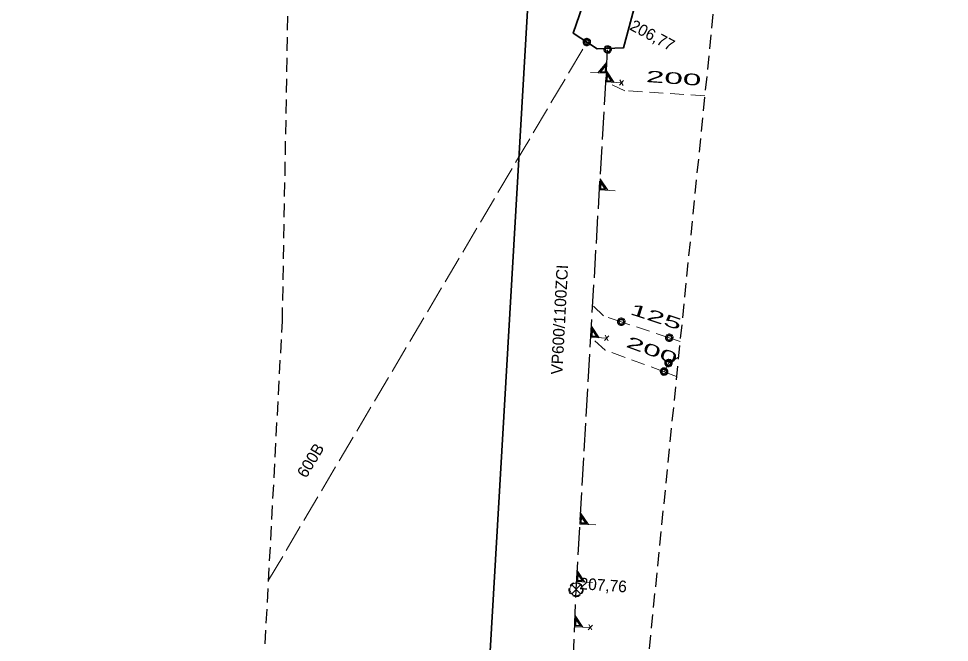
# Model space of a CAD drawing. Extents: x -744446 to -743929, y -1041261 to -1040599.
# Drawn here: x -744445.1 to -744380.7, y -1040960.6 to -1040917.5 of the extents above; entities that cross this region are included whole.
import ezdxf

# ---------------------------------------------------------------- set-up
doc = ezdxf.new("R2010")
doc.units = 0
doc.header["$LTSCALE"] = 0.32
doc.linetypes.add('LONG_DASHED', pattern=[7.5, 6, -1.5])
doc.linetypes.add('MEDIUM_DASHED', pattern=[4.5, 3, -1.5])
for name, color, linetype, lineweight in [('1', 7, 'MEDIUM_DASHED', 25), ('18', 7, 'Continuous', 13), ('20', 7, 'LONG_DASHED', 13), ('49', 7, 'MEDIUM_DASHED', 13)]:
    doc.layers.add(name, color=color, linetype=linetype, lineweight=lineweight)

msp = doc.modelspace()

# ---------------------------------------------------------------- linework, layer by layer
at = {"layer": '1'}
msp.add_lwpolyline([(-744438.077, -1041259.731), (-744438.679, -1041250.888), (-744445.125, -1041198.426), (-744434.434, -1041080.103), (-744426.87, -1040938.41), (-744425.446, -1040859.072), (-744414.192, -1040822.094), (-744390.076, -1040771.45), (-744357.118, -1040726.434), (-744307.278, -1040693.475), (-744241.36, -1040670.967), (-743937.498, -1040598.618), (-743928.655, -1040619.519), (-744129.684, -1040665.585), (-744218.109, -1040687.29), (-744311.358, -1040718.641), (-744361.198, -1040777.323), (-744391.745, -1040864.141), (-744411.355, -1041059.185), (-744416.379, -1041145.154), (-744432.569, -1041193.163), (-744432.047, -1041202.053), (-744422.803, -1041230.992), (-744424.813, -1041260.936)], close=True, dxfattribs=at)
at = {"layer": '18'}
for p, q in [((-744403.26, -1040921.749), (-744403.549, -1040922.068)), ((-744403.292, -1040922.086), (-744403.514, -1040921.701)), ((-744404.29, -1040939.429), (-744404.579, -1040939.748)), ((-744404.322, -1040939.766), (-744404.544, -1040939.381)), ((-744406.231, -1040957.285), (-744406.849, -1040956.667)), ((-744406.849, -1040957.285), (-744406.232, -1040956.668)), ((-744405.42, -1040959.451), (-744405.703, -1040959.774)), ((-744405.446, -1040959.788), (-744405.674, -1040959.407))]:
    msp.add_line(p, q, dxfattribs=at)
at = {"layer": '18', "lineweight": 35}
msp.add_lwpolyline([(-744405.436, -1040914.627), (-744403.633, -1040914.677), (-744402.237, -1040915.595), (-744403.265, -1040919.486), (-744405.096, -1040919.552), (-744406.737, -1040918.467)], close=True, dxfattribs=at)
at = {"layer": '18'}
for points in [[(-744405.537, -1040919.073), (-744405.543, -1040919.017), (-744405.559, -1040918.964), (-744405.588, -1040918.915), (-744405.627, -1040918.874), (-744405.673, -1040918.842), (-744405.725, -1040918.82), (-744405.78, -1040918.809), (-744405.836, -1040918.811), (-744405.891, -1040918.824), (-744405.941, -1040918.849), (-744405.986, -1040918.884), (-744406.022, -1040918.927), (-744406.047, -1040918.977), (-744406.062, -1040919.032), (-744406.065, -1040919.088), (-744406.056, -1040919.143), (-744406.035, -1040919.196), (-744406.004, -1040919.242), (-744405.963, -1040919.281), (-744405.916, -1040919.311), (-744405.863, -1040919.33), (-744405.807, -1040919.337), (-744405.75, -1040919.333), (-744405.696, -1040919.316), (-744405.647, -1040919.289), (-744405.606, -1040919.251), (-744405.573, -1040919.206), (-744405.549, -1040919.155), (-744405.538, -1040919.1)], [(-744405.596, -1040919.076), (-744405.602, -1040919.027), (-744405.62, -1040918.981), (-744405.647, -1040918.94), (-744405.684, -1040918.907), (-744405.728, -1040918.885), (-744405.777, -1040918.873), (-744405.826, -1040918.873), (-744405.874, -1040918.885), (-744405.918, -1040918.908), (-744405.955, -1040918.941), (-744405.983, -1040918.982), (-744406, -1040919.029), (-744406.005, -1040919.078), (-744405.999, -1040919.127), (-744405.981, -1040919.173), (-744405.953, -1040919.213), (-744405.916, -1040919.246), (-744405.872, -1040919.268), (-744405.823, -1040919.28), (-744405.774, -1040919.279), (-744405.726, -1040919.267), (-744405.683, -1040919.243), (-744405.646, -1040919.21), (-744405.618, -1040919.169), (-744405.602, -1040919.122)], [(-744405.655, -1040919.08), (-744405.661, -1040919.038), (-744405.678, -1040919), (-744405.706, -1040918.969), (-744405.74, -1040918.946), (-744405.781, -1040918.935), (-744405.823, -1040918.935), (-744405.863, -1040918.947), (-744405.897, -1040918.97), (-744405.924, -1040919.002), (-744405.941, -1040919.04), (-744405.946, -1040919.081), (-744405.941, -1040919.123), (-744405.923, -1040919.16), (-744405.895, -1040919.192), (-744405.858, -1040919.214), (-744405.819, -1040919.225), (-744405.777, -1040919.224), (-744405.737, -1040919.211), (-744405.703, -1040919.188), (-744405.676, -1040919.155), (-744405.66, -1040919.117)], [(-744404.097, -1040919.593), (-744404.103, -1040919.537), (-744404.12, -1040919.484), (-744404.149, -1040919.435), (-744404.187, -1040919.394), (-744404.233, -1040919.362), (-744404.285, -1040919.34), (-744404.34, -1040919.329), (-744404.396, -1040919.331), (-744404.451, -1040919.344), (-744404.502, -1040919.369), (-744404.546, -1040919.404), (-744404.582, -1040919.447), (-744404.607, -1040919.497), (-744404.622, -1040919.552), (-744404.625, -1040919.608), (-744404.616, -1040919.663), (-744404.595, -1040919.716), (-744404.564, -1040919.762), (-744404.524, -1040919.801), (-744404.476, -1040919.831), (-744404.423, -1040919.85), (-744404.367, -1040919.857), (-744404.311, -1040919.853), (-744404.257, -1040919.836), (-744404.208, -1040919.809), (-744404.166, -1040919.771), (-744404.133, -1040919.726), (-744404.11, -1040919.675), (-744404.098, -1040919.62)], [(-744404.156, -1040919.596), (-744404.162, -1040919.547), (-744404.18, -1040919.501), (-744404.208, -1040919.46), (-744404.245, -1040919.427), (-744404.289, -1040919.405), (-744404.337, -1040919.393), (-744404.386, -1040919.393), (-744404.434, -1040919.405), (-744404.478, -1040919.428), (-744404.515, -1040919.461), (-744404.543, -1040919.502), (-744404.56, -1040919.549), (-744404.566, -1040919.598), (-744404.559, -1040919.647), (-744404.541, -1040919.693), (-744404.513, -1040919.733), (-744404.476, -1040919.766), (-744404.432, -1040919.788), (-744404.383, -1040919.8), (-744404.334, -1040919.799), (-744404.286, -1040919.787), (-744404.243, -1040919.763), (-744404.206, -1040919.73), (-744404.178, -1040919.689), (-744404.162, -1040919.642)], [(-744404.215, -1040919.6), (-744404.221, -1040919.558), (-744404.238, -1040919.52), (-744404.266, -1040919.489), (-744404.301, -1040919.466), (-744404.341, -1040919.455), (-744404.383, -1040919.455), (-744404.423, -1040919.467), (-744404.458, -1040919.49), (-744404.485, -1040919.522), (-744404.502, -1040919.56), (-744404.507, -1040919.601), (-744404.501, -1040919.643), (-744404.483, -1040919.68), (-744404.455, -1040919.712), (-744404.419, -1040919.734), (-744404.379, -1040919.745), (-744404.337, -1040919.744), (-744404.297, -1040919.731), (-744404.263, -1040919.708), (-744404.236, -1040919.675), (-744404.22, -1040919.637)], [(-744403.153, -1040938.442), (-744403.159, -1040938.386), (-744403.176, -1040938.333), (-744403.205, -1040938.284), (-744403.243, -1040938.243), (-744403.289, -1040938.211), (-744403.341, -1040938.189), (-744403.396, -1040938.178), (-744403.452, -1040938.18), (-744403.507, -1040938.193), (-744403.558, -1040938.218), (-744403.602, -1040938.253), (-744403.638, -1040938.296), (-744403.663, -1040938.346), (-744403.678, -1040938.401), (-744403.681, -1040938.457), (-744403.672, -1040938.512), (-744403.651, -1040938.565), (-744403.62, -1040938.611), (-744403.58, -1040938.65), (-744403.532, -1040938.68), (-744403.479, -1040938.699), (-744403.423, -1040938.706), (-744403.367, -1040938.702), (-744403.313, -1040938.685), (-744403.264, -1040938.658), (-744403.222, -1040938.62), (-744403.189, -1040938.575), (-744403.166, -1040938.524), (-744403.154, -1040938.469)], [(-744403.212, -1040938.445), (-744403.218, -1040938.396), (-744403.236, -1040938.35), (-744403.264, -1040938.309), (-744403.301, -1040938.276), (-744403.345, -1040938.254), (-744403.393, -1040938.242), (-744403.442, -1040938.242), (-744403.49, -1040938.254), (-744403.534, -1040938.277), (-744403.571, -1040938.31), (-744403.599, -1040938.351), (-744403.616, -1040938.398), (-744403.622, -1040938.447), (-744403.615, -1040938.496), (-744403.597, -1040938.542), (-744403.569, -1040938.582), (-744403.532, -1040938.615), (-744403.488, -1040938.637), (-744403.439, -1040938.649), (-744403.39, -1040938.648), (-744403.342, -1040938.636), (-744403.299, -1040938.612), (-744403.262, -1040938.579), (-744403.234, -1040938.538), (-744403.218, -1040938.491)], [(-744403.271, -1040938.449), (-744403.277, -1040938.407), (-744403.294, -1040938.369), (-744403.322, -1040938.338), (-744403.357, -1040938.315), (-744403.397, -1040938.304), (-744403.439, -1040938.304), (-744403.479, -1040938.316), (-744403.514, -1040938.339), (-744403.541, -1040938.371), (-744403.558, -1040938.409), (-744403.563, -1040938.45), (-744403.557, -1040938.492), (-744403.539, -1040938.529), (-744403.511, -1040938.561), (-744403.475, -1040938.583), (-744403.435, -1040938.594), (-744403.393, -1040938.593), (-744403.353, -1040938.58), (-744403.319, -1040938.557), (-744403.292, -1040938.524), (-744403.276, -1040938.486)], [(-744399.831, -1040939.549), (-744399.837, -1040939.493), (-744399.853, -1040939.44), (-744399.882, -1040939.391), (-744399.921, -1040939.35), (-744399.967, -1040939.318), (-744400.019, -1040939.296), (-744400.074, -1040939.285), (-744400.13, -1040939.287), (-744400.184, -1040939.3), (-744400.235, -1040939.325), (-744400.28, -1040939.36), (-744400.316, -1040939.403), (-744400.341, -1040939.453), (-744400.356, -1040939.508), (-744400.358, -1040939.564), (-744400.35, -1040939.619), (-744400.329, -1040939.672), (-744400.298, -1040939.718), (-744400.257, -1040939.757), (-744400.21, -1040939.787), (-744400.157, -1040939.806), (-744400.101, -1040939.813), (-744400.044, -1040939.809), (-744399.99, -1040939.792), (-744399.941, -1040939.765), (-744399.9, -1040939.727), (-744399.867, -1040939.682), (-744399.843, -1040939.631), (-744399.831, -1040939.576)], [(-744399.89, -1040939.552), (-744399.896, -1040939.503), (-744399.914, -1040939.457), (-744399.941, -1040939.416), (-744399.978, -1040939.383), (-744400.022, -1040939.361), (-744400.071, -1040939.349), (-744400.12, -1040939.349), (-744400.168, -1040939.361), (-744400.212, -1040939.384), (-744400.249, -1040939.417), (-744400.277, -1040939.458), (-744400.294, -1040939.505), (-744400.299, -1040939.554), (-744400.293, -1040939.603), (-744400.275, -1040939.649), (-744400.247, -1040939.689), (-744400.21, -1040939.722), (-744400.166, -1040939.744), (-744400.117, -1040939.756), (-744400.068, -1040939.755), (-744400.02, -1040939.743), (-744399.977, -1040939.719), (-744399.94, -1040939.686), (-744399.912, -1040939.645), (-744399.896, -1040939.598)], [(-744399.949, -1040939.556), (-744399.955, -1040939.514), (-744399.972, -1040939.476), (-744400, -1040939.445), (-744400.034, -1040939.422), (-744400.075, -1040939.411), (-744400.117, -1040939.411), (-744400.157, -1040939.423), (-744400.191, -1040939.446), (-744400.218, -1040939.478), (-744400.235, -1040939.516), (-744400.24, -1040939.557), (-744400.235, -1040939.599), (-744400.217, -1040939.636), (-744400.189, -1040939.668), (-744400.152, -1040939.69), (-744400.113, -1040939.701), (-744400.071, -1040939.7), (-744400.031, -1040939.687), (-744399.997, -1040939.664), (-744399.97, -1040939.631), (-744399.954, -1040939.593)], [(-744399.884, -1040941.299), (-744399.89, -1040941.243), (-744399.907, -1040941.19), (-744399.936, -1040941.141), (-744399.974, -1040941.1), (-744400.02, -1040941.068), (-744400.072, -1040941.046), (-744400.127, -1040941.035), (-744400.183, -1040941.037), (-744400.238, -1040941.05), (-744400.289, -1040941.075), (-744400.333, -1040941.11), (-744400.369, -1040941.153), (-744400.394, -1040941.203), (-744400.409, -1040941.258), (-744400.412, -1040941.314), (-744400.403, -1040941.369), (-744400.382, -1040941.422), (-744400.351, -1040941.468), (-744400.311, -1040941.507), (-744400.263, -1040941.537), (-744400.21, -1040941.556), (-744400.154, -1040941.563), (-744400.098, -1040941.559), (-744400.044, -1040941.542), (-744399.995, -1040941.515), (-744399.953, -1040941.477), (-744399.92, -1040941.432), (-744399.897, -1040941.381), (-744399.885, -1040941.326)], [(-744399.943, -1040941.302), (-744399.949, -1040941.253), (-744399.967, -1040941.207), (-744399.995, -1040941.166), (-744400.032, -1040941.133), (-744400.076, -1040941.111), (-744400.124, -1040941.099), (-744400.173, -1040941.099), (-744400.221, -1040941.111), (-744400.265, -1040941.134), (-744400.302, -1040941.167), (-744400.33, -1040941.208), (-744400.347, -1040941.255), (-744400.353, -1040941.304), (-744400.346, -1040941.353), (-744400.328, -1040941.399), (-744400.3, -1040941.439), (-744400.263, -1040941.472), (-744400.219, -1040941.494), (-744400.17, -1040941.506), (-744400.121, -1040941.505), (-744400.073, -1040941.493), (-744400.03, -1040941.469), (-744399.993, -1040941.436), (-744399.965, -1040941.395), (-744399.949, -1040941.348)], [(-744400.002, -1040941.306), (-744400.008, -1040941.264), (-744400.025, -1040941.226), (-744400.053, -1040941.195), (-744400.088, -1040941.172), (-744400.128, -1040941.161), (-744400.17, -1040941.161), (-744400.21, -1040941.173), (-744400.245, -1040941.196), (-744400.272, -1040941.228), (-744400.289, -1040941.266), (-744400.294, -1040941.307), (-744400.288, -1040941.349), (-744400.27, -1040941.386), (-744400.242, -1040941.418), (-744400.206, -1040941.44), (-744400.166, -1040941.451), (-744400.124, -1040941.45), (-744400.084, -1040941.437), (-744400.05, -1040941.414), (-744400.023, -1040941.381), (-744400.007, -1040941.343)], [(-744400.194, -1040941.893), (-744400.2, -1040941.837), (-744400.217, -1040941.784), (-744400.245, -1040941.735), (-744400.284, -1040941.694), (-744400.33, -1040941.662), (-744400.382, -1040941.64), (-744400.437, -1040941.629), (-744400.493, -1040941.631), (-744400.548, -1040941.644), (-744400.598, -1040941.669), (-744400.643, -1040941.704), (-744400.679, -1040941.747), (-744400.704, -1040941.797), (-744400.719, -1040941.852), (-744400.722, -1040941.908), (-744400.713, -1040941.963), (-744400.692, -1040942.016), (-744400.661, -1040942.062), (-744400.62, -1040942.101), (-744400.573, -1040942.131), (-744400.52, -1040942.15), (-744400.464, -1040942.157), (-744400.407, -1040942.153), (-744400.353, -1040942.136), (-744400.304, -1040942.109), (-744400.263, -1040942.071), (-744400.23, -1040942.026), (-744400.206, -1040941.975), (-744400.195, -1040941.92)], [(-744400.253, -1040941.896), (-744400.259, -1040941.847), (-744400.277, -1040941.801), (-744400.304, -1040941.76), (-744400.342, -1040941.727), (-744400.386, -1040941.705), (-744400.434, -1040941.693), (-744400.483, -1040941.693), (-744400.531, -1040941.705), (-744400.575, -1040941.728), (-744400.612, -1040941.761), (-744400.64, -1040941.802), (-744400.657, -1040941.849), (-744400.663, -1040941.898), (-744400.656, -1040941.947), (-744400.638, -1040941.993), (-744400.61, -1040942.033), (-744400.573, -1040942.066), (-744400.529, -1040942.088), (-744400.48, -1040942.1), (-744400.431, -1040942.099), (-744400.383, -1040942.087), (-744400.34, -1040942.063), (-744400.303, -1040942.03), (-744400.275, -1040941.989), (-744400.259, -1040941.942)], [(-744400.312, -1040941.9), (-744400.318, -1040941.858), (-744400.335, -1040941.82), (-744400.363, -1040941.789), (-744400.397, -1040941.766), (-744400.438, -1040941.755), (-744400.48, -1040941.755), (-744400.52, -1040941.767), (-744400.554, -1040941.79), (-744400.581, -1040941.822), (-744400.598, -1040941.86), (-744400.603, -1040941.901), (-744400.598, -1040941.943), (-744400.58, -1040941.98), (-744400.552, -1040942.012), (-744400.516, -1040942.034), (-744400.476, -1040942.045), (-744400.434, -1040942.044), (-744400.394, -1040942.031), (-744400.36, -1040942.008), (-744400.333, -1040941.975), (-744400.317, -1040941.937)], [(-744406.103, -1040956.977), (-744406.106, -1040956.931), (-744406.113, -1040956.886), (-744406.125, -1040956.842), (-744406.141, -1040956.799), (-744406.162, -1040956.758), (-744406.187, -1040956.72), (-744406.216, -1040956.684), (-744406.248, -1040956.652), (-744406.284, -1040956.623), (-744406.322, -1040956.598), (-744406.363, -1040956.578), (-744406.406, -1040956.561), (-744406.45, -1040956.549), (-744406.495, -1040956.542), (-744406.541, -1040956.54), (-744406.587, -1040956.542), (-744406.632, -1040956.549), (-744406.676, -1040956.561), (-744406.719, -1040956.578), (-744406.76, -1040956.598), (-744406.798, -1040956.623), (-744406.834, -1040956.652), (-744406.866, -1040956.684), (-744406.895, -1040956.72), (-744406.92, -1040956.759), (-744406.941, -1040956.799), (-744406.956, -1040956.842), (-744406.969, -1040956.886), (-744406.976, -1040956.931), (-744406.978, -1040956.977), (-744406.976, -1040957.023), (-744406.969, -1040957.068), (-744406.956, -1040957.112), (-744406.941, -1040957.155), (-744406.92, -1040957.196), (-744406.895, -1040957.234), (-744406.866, -1040957.27), (-744406.834, -1040957.302), (-744406.798, -1040957.331), (-744406.76, -1040957.356), (-744406.719, -1040957.377), (-744406.676, -1040957.393), (-744406.632, -1040957.405), (-744406.587, -1040957.412), (-744406.541, -1040957.415), (-744406.495, -1040957.412), (-744406.45, -1040957.405), (-744406.406, -1040957.393), (-744406.363, -1040957.377), (-744406.322, -1040957.356), (-744406.284, -1040957.331), (-744406.248, -1040957.302), (-744406.216, -1040957.27), (-744406.187, -1040957.234), (-744406.162, -1040957.196), (-744406.141, -1040957.155), (-744406.125, -1040957.112), (-744406.113, -1040957.068), (-744406.106, -1040957.023)]]:
    msp.add_lwpolyline(points, close=True, dxfattribs=at)
for points in [[(-744405.547, -1040921.176), (-744404.453, -1040921.24), (-744404.408, -1040920.47), (-744405.03, -1040921.206)], [(-744404.909, -1040921.162), (-744404.494, -1040921.186), (-744404.461, -1040920.622), (-744404.91, -1040921.162)], [(-744404.822, -1040921.12), (-744404.532, -1040921.137), (-744404.51, -1040920.767), (-744404.822, -1040921.121)], [(-744403.399, -1040921.901), (-744404.492, -1040921.837), (-744404.447, -1040921.069), (-744403.915, -1040921.871)], [(-744404.031, -1040921.814), (-744404.445, -1040921.79), (-744404.412, -1040921.225), (-744404.029, -1040921.814)], [(-744404.111, -1040921.762), (-744404.402, -1040921.745), (-744404.381, -1040921.374), (-744404.111, -1040921.763)], [(-744403.832, -1040929.373), (-744404.926, -1040929.309), (-744404.881, -1040928.541), (-744404.349, -1040929.343)], [(-744404.464, -1040929.286), (-744404.879, -1040929.262), (-744404.846, -1040928.697), (-744404.463, -1040929.286)], [(-744404.545, -1040929.235), (-744404.836, -1040929.218), (-744404.814, -1040928.846), (-744404.545, -1040929.236)], [(-744404.429, -1040939.581), (-744405.522, -1040939.517), (-744405.477, -1040938.749), (-744404.945, -1040939.551)], [(-744405.061, -1040939.494), (-744405.475, -1040939.47), (-744405.442, -1040938.905), (-744405.059, -1040939.494)], [(-744405.141, -1040939.442), (-744405.432, -1040939.425), (-744405.411, -1040939.054), (-744405.141, -1040939.443)], [(-744405.181, -1040952.514), (-744406.275, -1040952.45), (-744406.23, -1040951.682), (-744405.698, -1040952.484)], [(-744405.813, -1040952.427), (-744406.228, -1040952.403), (-744406.195, -1040951.838), (-744405.812, -1040952.427)], [(-744405.894, -1040952.376), (-744406.185, -1040952.359), (-744406.163, -1040951.987), (-744405.894, -1040952.377)], [(-744405.413, -1040956.497), (-744406.507, -1040956.433), (-744406.462, -1040955.665), (-744405.93, -1040956.467)], [(-744406.045, -1040956.41), (-744406.46, -1040956.386), (-744406.427, -1040955.821), (-744406.044, -1040956.41)], [(-744406.126, -1040956.359), (-744406.417, -1040956.342), (-744406.395, -1040955.97), (-744406.126, -1040956.36)], [(-744407.037, -1040956.906), (-744407.043, -1040956.983), (-744407.038, -1040957.06), (-744407.021, -1040957.135), (-744406.992, -1040957.206), (-744406.951, -1040957.272), (-744406.936, -1040957.294)], [(-744406.692, -1040956.514), (-744406.763, -1040956.542), (-744406.83, -1040956.581), (-744406.89, -1040956.629), (-744406.941, -1040956.686), (-744406.965, -1040956.72)], [(-744406.151, -1040956.697), (-744406.201, -1040956.639), (-744406.259, -1040956.589), (-744406.324, -1040956.548), (-744406.395, -1040956.519), (-744406.444, -1040956.505)], [(-744406.156, -1040957.283), (-744406.115, -1040957.218), (-744406.084, -1040957.148), (-744406.065, -1040957.073), (-744406.057, -1040956.997), (-744406.062, -1040956.92), (-744406.068, -1040956.885)], [(-744406.779, -1040957.423), (-744406.709, -1040957.454), (-744406.634, -1040957.473), (-744406.558, -1040957.48), (-744406.481, -1040957.475), (-744406.406, -1040957.458), (-744406.334, -1040957.43), (-744406.274, -1040957.395)], [(-744405.556, -1040959.605), (-744406.65, -1040959.558), (-744406.617, -1040958.789), (-744406.072, -1040959.583)], [(-744406.189, -1040959.528), (-744406.604, -1040959.51), (-744406.58, -1040958.945), (-744406.187, -1040959.528)], [(-744406.27, -1040959.478), (-744406.562, -1040959.465), (-744406.546, -1040959.093), (-744406.27, -1040959.479)]]:
    msp.add_lwpolyline(points, dxfattribs=at)
at = {"layer": '20'}
msp.add_line((-744427.828, -1040956.346), (-744405.801, -1040919.086), dxfattribs=at)
at = {"layer": '20', "linetype": 'Continuous', "lineweight": 35}
msp.add_lwpolyline([(-744429.62, -1041252.21), (-744428.789, -1041237.94), (-744437.959, -1041195.193), (-744423.3, -1041145.69), (-744417.879, -1041053.98), (-744409.949, -1040917.67), (-744407.76, -1040880.01), (-744407.219, -1040869.23), (-744404.395, -1040847.829), (-744400.25, -1040827.35), (-744393.491, -1040807.621), (-744384.879, -1040787.9), (-744372.238, -1040768.547), (-744361.26, -1040752.62), (-744345.317, -1040736.555), (-744330.739, -1040723.14), (-744312.333, -1040710.859), (-744294.67, -1040700.75), (-744274.728, -1040692.583), (-744254.699, -1040686.49), (-744133.87, -1040657.39), (-743953.289, -1040613.85), (-743946.017, -1040612.141)], dxfattribs=at)
at = {"layer": '20', "lineweight": 25}
msp.add_lwpolyline([(-744408.243, -1040993.153), (-744407.177, -1040971.928), (-744406.539, -1040956.977), (-744404.361, -1040919.606)], dxfattribs=at)
at = {"layer": '49'}
for p, q in [((-744400.148, -1040941.312), (-744400.458, -1040941.906)), ((-744399.463, -1040940.9), (-744400.148, -1040941.312)), ((-744399.596, -1040942.223), (-744400.458, -1040941.906))]:
    msp.add_line(p, q, dxfattribs=at)
for points in [[(-744397.642, -1040922.794), (-744403.182, -1040922.444), (-744404.491, -1040921.843)], [(-744403.417, -1040938.455), (-744404.658, -1040938.042), (-744405.392, -1040937.303)], [(-744399.353, -1040939.809), (-744400.095, -1040939.562), (-744403.417, -1040938.455)], [(-744400.458, -1040941.906), (-744404.537, -1040940.404), (-744405.521, -1040939.523)]]:
    msp.add_lwpolyline(points, dxfattribs=at)

# ---------------------------------------------------------------- texts
at = {"layer": '1'}
for s, rotation, p in [('206,77', 332, (-744402.892, -1040918.191)), ('VP600/1100ZCI ', 87, (-744407.492, -1040942.119)), ('600B', 59, (-744425.224, -1040949.321)), ('207,76', 356, (-744406.326, -1040956.959))]:
    msp.add_text(s, height=0.8, rotation=rotation, dxfattribs=at).set_placement(p)
for s, rotation, width, p in [('200 ', 356, 2.15, (-744401.737, -1040921.838)), ('125 ', 342, 2.05, (-744402.881, -1040937.903)), ('200 ', 340, 2.05, (-744403.146, -1040940.163))]:
    msp.add_text(s, height=0.8, rotation=rotation, dxfattribs=dict(at, width=width)).set_placement(p)

doc.saveas('drawing.dxf')
